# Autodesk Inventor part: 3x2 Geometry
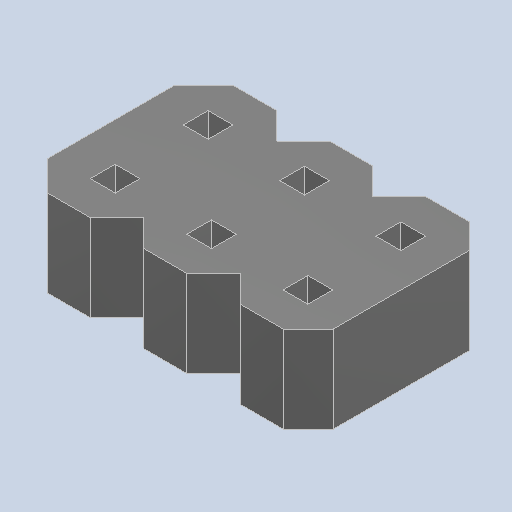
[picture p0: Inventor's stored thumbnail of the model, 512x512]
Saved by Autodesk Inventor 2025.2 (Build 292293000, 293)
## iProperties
Created: 2025-04
Part Number: 3x2 Geometry
Material: Generic
Description: PART-3x2 Geometry-DESC
Document SubType Name: Modeling
Designer: BennF
Density: 1 g/cm^3
Appearance: Default
Author: BennF
Revision Number: NONE
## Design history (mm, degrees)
feature "3x2"
body "Solid1"
